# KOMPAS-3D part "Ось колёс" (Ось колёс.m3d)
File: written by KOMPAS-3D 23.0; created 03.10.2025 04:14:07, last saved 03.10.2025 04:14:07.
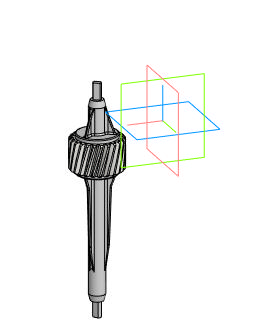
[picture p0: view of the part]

Document properties: Автор: Lost; Полное имя файла: C:\Users\Lost\Downloads\Telegram Desktop\ИМ-ИТ ЦД\ИМ-ИТ ЦД\Вариант 12\Ось колёс.m3d

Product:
- Part/product: Ось колёс

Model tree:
1. Операция без истории:1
